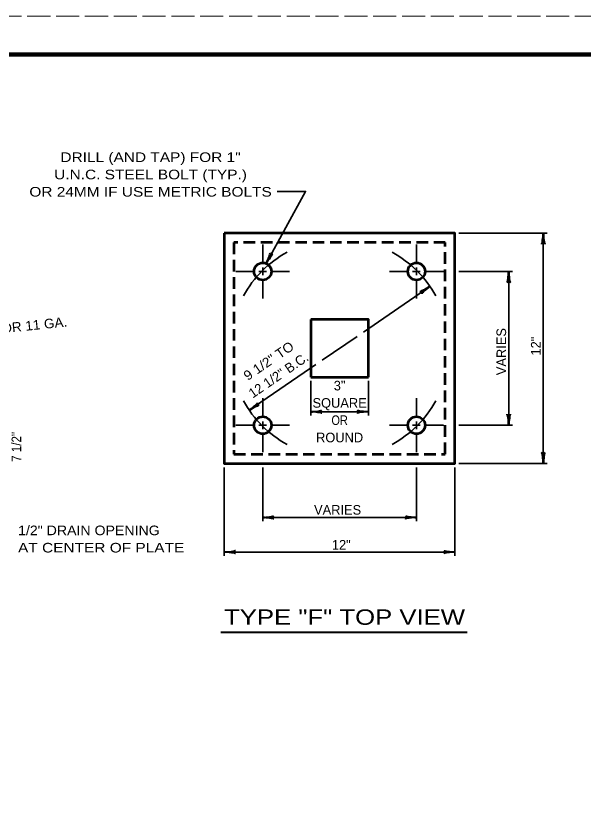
# Model space of a CAD drawing. Extents: x -1 to 679, y 0 to 440.
# Drawn here: x 288.2 to 436, y 231 to 439.6 of the extents above; entities that cross this region are included whole.
import ezdxf
from ezdxf.enums import TextEntityAlignment as Align

# ---------------------------------------------------------------- set-up
doc = ezdxf.new("R2010")
doc.units = 0
doc.linetypes.add('LONG_DASHED', pattern=[7.5, 6, -1.5])
doc.linetypes.add('MEDIUM_DASHED', pattern=[4.5, 3, -1.5])
doc.layers.add('1', color=7, linetype='Continuous', lineweight=53)
doc.layers.add('61', color=7, linetype='Continuous', lineweight=35)

msp = doc.modelspace()

# ---------------------------------------------------------------- linework, layer by layer
at = {"layer": '1', "lineweight": 35}
for p, q in [((403.388, 383.171), (426.388, 383.171)), ((425.388, 383.171), (425.388, 323.171)), ((352.388, 375.171), (352.388, 380.171)), ((392.388, 375.171), (392.388, 380.171)), ((352.388, 374.171), (352.388, 372.171)), ((392.388, 372.171), (392.388, 374.171)), ((350.388, 373.171), (345.388, 373.171)), ((353.388, 373.171), (351.388, 373.171)), ((354.388, 373.171), (359.388, 373.171)), ((390.388, 373.171), (385.388, 373.171)), ((393.388, 373.171), (391.388, 373.171)), ((394.388, 373.171), (399.388, 373.171)), ((403.388, 373.171), (417.388, 373.171)), ((416.388, 373.171), (416.388, 333.171)), ((352.388, 371.171), (352.388, 366.171)), ((392.388, 371.171), (392.388, 366.171)), ((378.572, 357.414), (395.888, 369.296)), ((367.852, 350.059), (376.923, 356.283)), ((348.888, 337.047), (366.203, 348.928)), ((364.888, 344.671), (364.888, 335.671)), ((379.888, 344.671), (379.888, 335.671)), ((352.388, 335.171), (352.388, 340.171)), ((392.388, 335.171), (392.388, 340.171)), ((364.888, 336.671), (379.888, 336.671)), ((352.388, 334.171), (352.388, 332.171)), ((392.388, 332.171), (392.388, 334.171)), ((350.388, 333.171), (345.388, 333.171)), ((351.388, 333.171), (353.388, 333.171)), ((354.388, 333.171), (359.388, 333.171)), ((390.388, 333.171), (385.388, 333.171)), ((391.388, 333.171), (393.388, 333.171)), ((394.388, 333.171), (399.388, 333.171)), ((403.388, 333.171), (417.388, 333.171)), ((352.388, 331.171), (352.388, 326.171)), ((392.388, 331.171), (392.388, 326.171)), ((342.388, 322.171), (342.388, 299.171)), ((352.388, 322.171), (352.388, 308.171)), ((392.388, 322.171), (392.388, 308.171)), ((402.388, 322.171), (402.388, 299.171)), ((403.388, 323.171), (426.388, 323.171)), ((352.388, 309.171), (392.388, 309.171)), ((342.388, 300.171), (402.388, 300.171))]:
    msp.add_line(p, q, dxfattribs=at)
at = {"layer": '1', "linetype": 'MEDIUM_DASHED'}
for p, q in [((344.888, 380.671), (344.888, 325.671)), ((399.888, 380.671), (344.888, 380.671)), ((399.888, 325.671), (399.888, 380.671)), ((344.888, 325.671), (399.888, 325.671))]:
    msp.add_line(p, q, dxfattribs=at)
at = {"layer": '1'}
for p, q in [((364.888, 360.671), (364.888, 345.671)), ((364.888, 345.671), (379.888, 345.671))]:
    msp.add_line(p, q, dxfattribs=at)
at = {"layer": '1', "lineweight": 40}
msp.add_line((341.489, 279.304), (405.563, 279.304), dxfattribs=at)
at = {"layer": '1', "lineweight": 35}
msp.add_lwpolyline([(353.265, 375.243), (363.53, 394.003), (356.104, 394.003)], dxfattribs=at)
at = {"layer": '1'}
msp.add_lwpolyline([(342.388, 383.171), (342.388, 323.171), (402.388, 323.171), (402.388, 383.171)], close=True, dxfattribs=at)
msp.add_lwpolyline([(379.888, 345.671), (379.888, 360.671), (364.888, 360.671)], dxfattribs=at)
for centre in [(352.388, 373.171), (392.388, 373.171), (352.388, 333.171), (392.388, 333.171)]:
    msp.add_circle(centre, 2.25, dxfattribs=at)
at = {"layer": '1', "lineweight": 35}
for start, end in [(118.69441, 151.30559), (28.69441, 61.30559), (208.69441, 241.30559), (298.69441, 331.30559)]:
    msp.add_arc((372.388, 353.171), 28.5, start, end, dxfattribs=at)
at = {"layer": '1', "lineweight": 40}
for centre, major_axis, ratio, start_param, end_param in [((425.176, 382.051), (0.176, 1.756), 0.07063, 3.1407148, 5.41811), ((425.176, 382.051), (0.176, 1.756), 0.07063, 3.1407148, 5.41811), ((425.664, 382.08), (-0.156, 1.786), 0.122415, 0.8963533, 3.1415927), ((425.664, 382.08), (-0.156, 1.786), 0.122415, 0.8963533, 3.1415927), ((353.546, 376.333), (-0.72, -1.641), 0.122415, 0.8963533, 3.1415927), ((353.988, 376.124), (0.997, 1.457), 0.07063, 6.2823074, 8.5597026), ((416.176, 372.051), (0.176, 1.756), 0.07063, 3.1407148, 5.41811), ((416.176, 372.051), (0.176, 1.756), 0.07063, 3.1407148, 5.41811), ((416.664, 372.08), (-0.156, 1.786), 0.122415, 0.8963533, 3.1415927), ((416.664, 372.08), (-0.156, 1.786), 0.122415, 0.8963533, 3.1415927), ((394.844, 368.836), (1.548, 0.849), 0.07063, 3.1407148, 5.41811), ((395.144, 368.45), (1.384, 1.139), 0.122415, 0.8963533, 3.1415927), ((349.631, 337.892), (-1.384, -1.139), 0.122415, 0.8963533, 3.1415927), ((349.931, 337.506), (-1.548, -0.849), 0.07063, 3.1407148, 5.41811), ((366.008, 336.459), (-1.756, 0.176), 0.07063, 3.1407148, 5.41811), ((366.008, 336.459), (-1.756, 0.176), 0.07063, 3.1407148, 5.41811), ((365.979, 336.947), (-1.786, -0.156), 0.122415, 0.8963533, 3.1415927), ((365.979, 336.947), (-1.786, -0.156), 0.122415, 0.8963533, 3.1415927), ((378.796, 336.395), (1.786, 0.156), 0.122415, 0.8963533, 3.1415927), ((378.767, 336.883), (1.756, -0.176), 0.07063, 3.1407148, 5.41811), ((416.111, 334.262), (0.156, -1.786), 0.122415, 0.8963533, 3.1415927), ((416.111, 334.262), (0.156, -1.786), 0.122415, 0.8963533, 3.1415927), ((416.599, 334.292), (-0.176, -1.756), 0.07063, 3.1407148, 5.41811), ((416.599, 334.292), (-0.176, -1.756), 0.07063, 3.1407148, 5.41811), ((425.111, 324.262), (0.156, -1.786), 0.122415, 0.8963533, 3.1415927), ((425.599, 324.292), (-0.176, -1.756), 0.07063, 3.1407148, 5.41811), ((353.508, 308.959), (-1.756, 0.176), 0.07063, 3.1407148, 5.41811), ((353.508, 308.959), (-1.756, 0.176), 0.07063, 3.1407148, 5.41811), ((353.479, 309.447), (-1.786, -0.156), 0.122415, 0.8963533, 3.1415927), ((353.479, 309.447), (-1.786, -0.156), 0.122415, 0.8963533, 3.1415927), ((391.296, 308.895), (1.786, 0.156), 0.122415, 0.8963533, 3.1415927), ((391.296, 308.895), (1.786, 0.156), 0.122415, 0.8963533, 3.1415927), ((391.267, 309.383), (1.756, -0.176), 0.07063, 3.1407148, 5.41811), ((391.267, 309.383), (1.756, -0.176), 0.07063, 3.1407148, 5.41811), ((343.479, 300.447), (-1.786, -0.156), 0.122415, 0.8963533, 3.1415927), ((401.267, 300.383), (1.756, -0.176), 0.07063, 3.1407148, 5.41811), ((401.267, 300.383), (1.756, -0.176), 0.07063, 3.1407148, 5.41811), ((343.508, 299.959), (-1.756, 0.176), 0.07063, 3.1407148, 5.41811), ((401.296, 299.895), (1.786, 0.156), 0.122415, 0.8963533, 3.1415927), ((401.296, 299.895), (1.786, 0.156), 0.122415, 0.8963533, 3.1415927)]:
    msp.add_ellipse(centre, major_axis=major_axis, ratio=ratio, start_param=start_param, end_param=end_param, dxfattribs=at)
at = {"layer": '61', "linetype": 'LONG_DASHED', "lineweight": 13}
msp.add_line((-1.376, 439.629), (678.644, 439.629), dxfattribs=at)
at = {"layer": '61', "lineweight": 158}
msp.add_lwpolyline([(667.664, 429.629), (28.624, 429.629), (28.624, 9.609)], dxfattribs=at)

# ---------------------------------------------------------------- texts
at = {"layer": '1'}
for s, height, width, p in [('DRILL (AND TAP) FOR 1"', 2.5, 1.2, (323.194, 401.65)), ('U.N.C. STEEL BOLT (TYP.)', 2.5, 1.2, (323.194, 397.15)), ('OR 24MM IF USE METRIC BOLTS', 2.5, 1.2, (323.194, 392.65)), ('OR', 2.5, 0.85, (372.388, 333.22)), ('TYPE "F" TOP VIEW', 4, 1.25, (373.677, 281.237))]:
    msp.add_text(s, height=height, dxfattribs=dict(at, width=width)).set_placement(p, align=Align.CENTER)
for s, rotation, width, p in [('1/4" OR 11 GA.', 6, 1.05, (289.539, 357.603)), ('9 1/2" TO', 34.456, 1.05, (354.638, 348.875)), ('7 1/2"', 90, 0.9, (289.533, 327.537))]:
    msp.add_text(s, height=2.5, rotation=rotation, dxfattribs=dict(at, width=width)).set_placement(p, align=Align.CENTER)
for s, rotation, p in [('VARIES', 90, (415.707, 352.314)), ('12"', 90, (424.679, 353.75)), ('12 1/2" B.C.', 34.456, (357.184, 345.165))]:
    msp.add_text(s, height=2.5, rotation=rotation, dxfattribs=at).set_placement(p, align=Align.CENTER)
for s, p in [('3"', (372.388, 342.22)), ('SQUARE', (372.388, 337.72)), ('ROUND', (372.388, 328.72)), ('VARIES', (371.87, 309.899)), ('12"', (372.827, 300.805))]:
    msp.add_text(s, height=2.5, dxfattribs=at).set_placement(p, align=Align.CENTER)
for s, width, p in [('1/2" DRAIN OPENING', 1.1, (288.722, 304.55)), ('AT CENTER OF PLATE', 1.2, (288.722, 300.05))]:
    msp.add_text(s, height=2.5, dxfattribs=dict(at, width=width)).set_placement(p)

doc.saveas('drawing.dxf')
